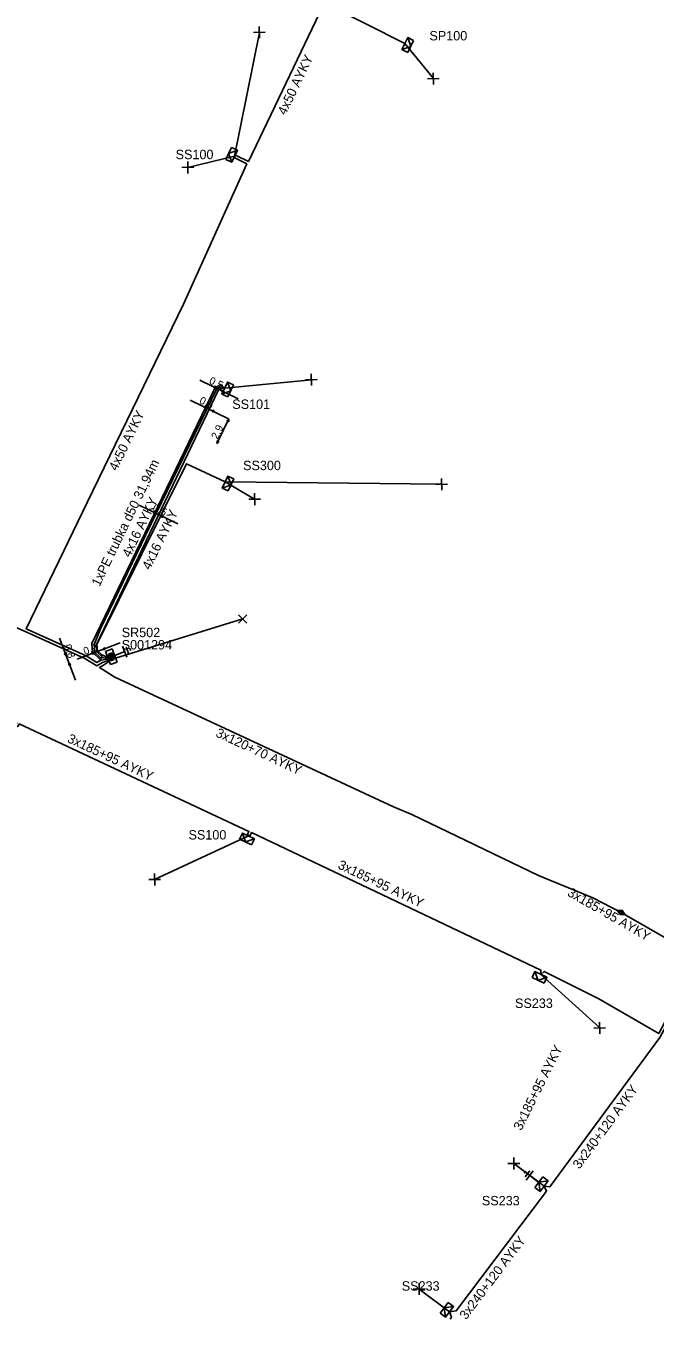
# Model space of a CAD drawing. Extents: x -762500 to -761285, y -1155006 to -1154135.
# Drawn here: x -762111.4 to -762044.9, y -1155000 to -1154863.6 of the extents above; entities that cross this region are included whole.
import ezdxf

# ---------------------------------------------------------------- set-up
doc = ezdxf.new("R2010")
doc.units = 0
for name, color, linetype in [('Vrstva 15', 7, 'Continuous'), ('Vrstva 19', 7, 'Continuous'), ('Vrstva 20', 7, 'Continuous'), ('Vrstva 21', 7, 'Continuous'), ('Vrstva 28', 7, 'Continuous'), ('Vrstva 29', 7, 'Continuous'), ('Vrstva 30', 7, 'Continuous'), ('Vrstva 31', 7, 'Continuous'), ('Vrstva 33', 7, 'Continuous'), ('Vrstva 34', 7, 'Continuous'), ('Vrstva 40', 7, 'Continuous'), ('Vrstva 5', 7, 'Continuous'), ('Vrstva 52', 7, 'Continuous'), ('Vrstva 54', 7, 'Continuous'), ('Vrstva 59', 7, 'Continuous'), ('Vrstva 6', 7, 'Continuous')]:
    doc.layers.add(name, color=color, linetype=linetype)

msp = doc.modelspace()

# ---------------------------------------------------------------- linework, layer by layer
at = {"layer": 'Vrstva 15'}
for points in [[(-762102.074, -1154930.026), (-762100.907, -1154929.578)], [(-762101.131, -1154928.995), (-762100.683, -1154930.162)], [(-762100.755, -1154929.109), (-762100.473, -1154929.844)], [(-762100.372, -1154929.23), (-762100.324, -1154929.354)], [(-762100.324, -1154929.354), (-762100.278, -1154929.474)], [(-762058.711, -1154984.596), (-762058.631, -1154984.49)], [(-762058.631, -1154984.49), (-762058.554, -1154984.388)], [(-762058.61, -1154984.986), (-762058.136, -1154984.358)], [(-762058.508, -1154985.366), (-762057.756, -1154984.367)], [(-762057.133, -1154985.619), (-762058.132, -1154984.866)]]:
    msp.add_lwpolyline(points, dxfattribs=at)
at = {"layer": 'Vrstva 19'}
for points in [[(-762048.601, -1154957.329), (-762048.042, -1154957.351), (-762048.359, -1154956.892), (-762048.917, -1154956.867), (-762048.601, -1154957.329)], [(-762048.157, -1154957.292), (-762048.39, -1154956.947), (-762048.796, -1154956.933), (-762048.571, -1154957.274), (-762048.157, -1154957.292)], [(-762048.268, -1154957.231), (-762048.42, -1154957.002), (-762048.702, -1154956.99), (-762048.54, -1154957.219), (-762048.268, -1154957.231)], [(-762048.374, -1154957.172), (-762048.451, -1154957.057), (-762048.595, -1154957.05), (-762048.51, -1154957.164), (-762048.374, -1154957.172)]]:
    msp.add_lwpolyline(points, dxfattribs=at)
at = {"layer": 'Vrstva 20'}
msp.add_lwpolyline([(-762090.7, -1154901.42), (-762091.37, -1154901.71), (-762104.4, -1154928.74), (-762104.3, -1154929.65), (-762103.52, -1154930.42), (-762103.26, -1154930.18), (-762103.84, -1154929.61), (-762103.9, -1154928.83), (-762091, -1154901.97), (-762090.52, -1154901.77)], close=True, dxfattribs=at)
at = {"layer": 'Vrstva 28'}
for points in [[(-762102.242, -1154929.29), (-762102.942, -1154929.559)], [(-762102.942, -1154929.559), (-762102.405, -1154930.96)], [(-762102.281, -1154929.716), (-762102.634, -1154929.852)], [(-762102.634, -1154929.852), (-762102.367, -1154930.547)], [(-762102.308, -1154929.777), (-762102.573, -1154929.879)], [(-762102.573, -1154929.879), (-762102.34, -1154930.486)], [(-762102.335, -1154929.839), (-762102.512, -1154929.906)], [(-762102.512, -1154929.906), (-762102.313, -1154930.425)], [(-762102.363, -1154929.9), (-762102.451, -1154929.933)], [(-762102.451, -1154929.933), (-762102.286, -1154930.364)], [(-762102.256, -1154930.308), (-762102.392, -1154929.955)], [(-762102.198, -1154930.33), (-762102.363, -1154929.9)], [(-762102.136, -1154930.357), (-762102.335, -1154929.839)], [(-762102.075, -1154930.384), (-762102.308, -1154929.777)], [(-762102.014, -1154930.411), (-762102.281, -1154929.716)], [(-762101.705, -1154930.691), (-762102.242, -1154929.29)], [(-762102.405, -1154930.96), (-762101.705, -1154930.691)], [(-762102.367, -1154930.547), (-762102.014, -1154930.411)], [(-762102.34, -1154930.486), (-762102.075, -1154930.384)], [(-762102.313, -1154930.425), (-762102.136, -1154930.357)], [(-762102.286, -1154930.364), (-762102.198, -1154930.33)]]:
    msp.add_lwpolyline(points, dxfattribs=at)
at = {"layer": 'Vrstva 31'}
for points in [[(-762071.009, -1154866.359), (-762071.638, -1154866.052), (-762071.024, -1154864.794), (-762070.395, -1154865.101)], [(-762070.702, -1154865.73), (-762071.638, -1154866.052)], [(-762070.702, -1154865.73), (-762071.024, -1154864.794)], [(-762071.009, -1154866.359), (-762070.395, -1154865.101)], [(-762089.648, -1154876.397), (-762090.24, -1154877.666)], [(-762089.648, -1154876.397), (-762089.014, -1154876.693), (-762089.605, -1154877.961), (-762090.24, -1154877.666)], [(-762089.944, -1154877.031), (-762089.014, -1154876.693)], [(-762089.944, -1154877.031), (-762089.605, -1154877.961)], [(-762090.013, -1154902.713), (-762090.647, -1154902.417), (-762090.055, -1154901.148), (-762089.421, -1154901.444)], [(-762089.717, -1154902.078), (-762090.055, -1154901.148)], [(-762090.013, -1154902.713), (-762089.421, -1154901.444)], [(-762089.717, -1154902.078), (-762090.647, -1154902.417)], [(-762089.972, -1154912.623), (-762090.606, -1154912.327), (-762090.015, -1154911.059), (-762089.38, -1154911.354)], [(-762089.676, -1154911.989), (-762090.015, -1154911.059)], [(-762089.676, -1154911.989), (-762090.606, -1154912.327)], [(-762089.972, -1154912.623), (-762089.38, -1154911.354)], [(-762088.783, -1154949.367), (-762088.487, -1154948.733), (-762087.218, -1154949.325), (-762087.514, -1154949.959)], [(-762088.148, -1154949.663), (-762088.487, -1154948.733)], [(-762088.783, -1154949.367), (-762087.514, -1154949.959)], [(-762088.148, -1154949.663), (-762087.218, -1154949.325)], [(-762057.893, -1154963.978), (-762057.597, -1154963.344), (-762056.328, -1154963.935), (-762056.624, -1154964.57)], [(-762057.893, -1154963.978), (-762056.624, -1154964.57)], [(-762057.258, -1154964.274), (-762057.597, -1154963.344)], [(-762057.258, -1154964.274), (-762056.328, -1154963.935)], [(-762056.756, -1154985.017), (-762057.599, -1154986.135)], [(-762056.756, -1154985.017), (-762056.197, -1154985.438), (-762057.04, -1154986.557), (-762057.599, -1154986.135)], [(-762057.178, -1154985.576), (-762056.197, -1154985.438)], [(-762057.178, -1154985.576), (-762057.04, -1154986.557)], [(-762066.756, -1154998.267), (-762067.599, -1154999.385)], [(-762066.756, -1154998.267), (-762066.197, -1154998.688), (-762067.04, -1154999.807), (-762067.599, -1154999.385)], [(-762067.178, -1154998.826), (-762066.197, -1154998.688)], [(-762067.178, -1154998.826), (-762067.04, -1154999.807)]]:
    msp.add_lwpolyline(points, dxfattribs=at)
at = {"layer": 'Vrstva 34'}
for points in [[(-762087.315, -1154864.261), (-762086.065, -1154864.239)], [(-762086.679, -1154864.875), (-762086.701, -1154863.625)], [(-762068.299, -1154869.755), (-762068.321, -1154868.505)], [(-762068.935, -1154869.141), (-762067.685, -1154869.119)], [(-762094.239, -1154879.125), (-762094.261, -1154877.875)], [(-762094.875, -1154878.511), (-762093.625, -1154878.489)], [(-762081.825, -1154900.911), (-762080.575, -1154900.889)], [(-762081.189, -1154901.525), (-762081.211, -1154900.275)], [(-762068.055, -1154911.941), (-762066.805, -1154911.919)], [(-762067.419, -1154912.555), (-762067.441, -1154911.305)], [(-762087.815, -1154913.511), (-762086.565, -1154913.489)], [(-762087.179, -1154914.125), (-762087.201, -1154912.875)], [(-762088.882, -1154925.688), (-762087.998, -1154926.572)], [(-762088.882, -1154926.572), (-762087.998, -1154925.688)], [(-762097.739, -1154954.255), (-762097.761, -1154953.005)], [(-762098.375, -1154953.641), (-762097.125, -1154953.619)], [(-762051.375, -1154969.301), (-762050.125, -1154969.279)], [(-762050.739, -1154969.915), (-762050.761, -1154968.665)], [(-762059.799, -1154984.215), (-762059.821, -1154982.965)], [(-762060.435, -1154983.601), (-762059.185, -1154983.579)], [(-762070.435, -1154996.851), (-762069.185, -1154996.829)], [(-762069.799, -1154997.465), (-762069.821, -1154996.215)]]:
    msp.add_lwpolyline(points, dxfattribs=at)
at = {"layer": 'Vrstva 40'}
for points in [[(-762088.94, -1154902.92), (-762092.97, -1154900.95)], [(-762089.96, -1154905.01), (-762094, -1154903.04)], [(-762091.17, -1154907.63), (-762089.9, -1154905.04)], [(-762099.39, -1154914.15), (-762095.31, -1154916.09)], [(-762106.1, -1154932.6), (-762107.8, -1154928.15)], [(-762101.39, -1154928.66), (-762105.94, -1154930.39)]]:
    msp.add_lwpolyline(points, dxfattribs=at)
for points in [[(-762091.168, -1154901.831), (-762091.437, -1154901.821), (-762091.349, -1154901.631)], [(-762090.742, -1154902.039), (-762090.473, -1154902.049), (-762090.561, -1154902.239)], [(-762092.198, -1154903.921), (-762092.467, -1154903.911), (-762092.379, -1154903.721)], [(-762091.762, -1154904.139), (-762091.493, -1154904.149), (-762091.581, -1154904.339)], [(-762089.899, -1154905.038), (-762089.909, -1154905.307), (-762090.099, -1154905.219)], [(-762091.171, -1154907.632), (-762091.161, -1154907.363), (-762090.971, -1154907.451)], [(-762097.578, -1154915.011), (-762097.847, -1154915.001), (-762097.759, -1154914.811)], [(-762097.122, -1154915.229), (-762096.853, -1154915.239), (-762096.941, -1154915.429)], [(-762107.089, -1154930.023), (-762107.276, -1154929.828), (-762107.08, -1154929.753)], [(-762104.068, -1154929.679), (-762104.262, -1154929.866), (-762104.337, -1154929.671)], [(-762103.262, -1154929.371), (-762103.068, -1154929.184), (-762102.993, -1154929.379)], [(-762106.82, -1154930.728), (-762106.634, -1154930.922), (-762106.829, -1154930.997)]]:
    msp.add_lwpolyline(points, close=True, dxfattribs=at)
at = {"layer": 'Vrstva 5'}
for points in [[(-762102.72, -1154930.4), (-762103.42, -1154930.5), (-762103.86, -1154930.73), (-762104.97, -1154930.03), (-762111.33, -1154927.18), (-762104.86, -1154913.86), (-762094.7, -1154892.93), (-762088.02, -1154878.13), (-762089.28, -1154877.5), (-762089.31, -1154877.33), (-762089.14, -1154877.24), (-762087.84, -1154877.87), (-762077.14, -1154855.52), (-762078.88, -1154854.61), (-762079.02, -1154854.2)], [(-762079.02, -1154854.2), (-762076.74, -1154855.39), (-762079.56, -1154861.27), (-762071.33, -1154865.42)], [(-762102.85, -1154930.14), (-762103.31, -1154929.93), (-762103.77, -1154929.52), (-762103.86, -1154928.82), (-762094.39, -1154909.77), (-762090.31, -1154911.69)], [(-762128.78, -1154919.4), (-762128.84, -1154919.72), (-762110.73, -1154927.77), (-762105.11, -1154930.3), (-762103.87, -1154931.08), (-762103.27, -1154930.75), (-762102.67, -1154930.54)], [(-762135.97, -1154927.36), (-762135.55, -1154926.14), (-762112.32, -1154937.09), (-762112.43, -1154937.34), (-762112.35, -1154937.52), (-762112.16, -1154937.46), (-762112.05, -1154937.21), (-762087.8, -1154948.55), (-762087.93, -1154948.83), (-762087.85, -1154949.03), (-762087.66, -1154948.97), (-762087.52, -1154948.67), (-762056.95, -1154963.18), (-762056.96, -1154963.64)], [(-762102.61, -1154930.68), (-762103.14, -1154931.02), (-762103.59, -1154931.26), (-762101.97, -1154932.27), (-762072.52, -1154945.96), (-762070.58, -1154946.78), (-762057.2, -1154953.22), (-762051.46, -1154955.56), (-762048.48, -1154957.11)], [(-762048.48, -1154957.11), (-762040.57, -1154961.64), (-762040.21, -1154961.46)], [(-762039.98, -1154961.58), (-762039.86, -1154961.99), (-762044.4, -1154970.29), (-762056.02, -1154986.07), (-762056.62, -1154986), (-762056.37, -1154986.51), (-762065.89, -1154999.15), (-762066.62, -1154999.25)], [(-762056.96, -1154963.64), (-762056.61, -1154963.33), (-762050.84, -1154966.21), (-762044.51, -1154969.87), (-762040.1, -1154961.52)], [(-762066.62, -1154999.25), (-762066.4, -1154999.8), (-762066.55, -1155000)]]:
    msp.add_lwpolyline(points, dxfattribs=at)
at = {"layer": 'Vrstva 52'}
msp.add_lwpolyline([(-762102.78, -1154930.26), (-762103.5, -1154930.2), (-762104.07, -1154929.68), (-762104.15, -1154928.85), (-762103.45, -1154927.11), (-762098.7, -1154917.33), (-762091.17, -1154901.83), (-762090.66, -1154901.62), (-762090.35, -1154901.78)], dxfattribs=at)
at = {"layer": 'Vrstva 59'}
for points in [[(-762089.31, -1154877.33), (-762086.69, -1154864.25)], [(-762071.33, -1154865.42), (-762068.31, -1154869.13)], [(-762089.31, -1154877.33), (-762094.25, -1154878.5)], [(-762090.35, -1154901.78), (-762081.2, -1154900.9)], [(-762090.31, -1154911.69), (-762067.43, -1154911.93)], [(-762090.31, -1154911.69), (-762087.19, -1154913.5)], [(-762101.87, -1154930.28), (-762088.44, -1154926.13)], [(-762087.85, -1154949.03), (-762097.75, -1154953.63)], [(-762056.96, -1154963.64), (-762050.75, -1154969.29)], [(-762056.62, -1154986), (-762059.81, -1154983.59)], [(-762066.62, -1154999.25), (-762069.81, -1154996.84)]]:
    msp.add_lwpolyline(points, dxfattribs=at)

# ---------------------------------------------------------------- texts
at = {"layer": 'Vrstva 21'}
msp.add_text('1xPE trubka d50 31,94m', height=0.99429, rotation=64.26411, dxfattribs=at).set_placement((-762103.57, -1154922.79))
at = {"layer": 'Vrstva 29'}
msp.add_text('S001294', height=0.9943, dxfattribs=at).set_placement((-762101.23, -1154929.36))
at = {"layer": 'Vrstva 30'}
msp.add_text('SR502', height=0.9943, dxfattribs=at).set_placement((-762101.23, -1154928.06))
at = {"layer": 'Vrstva 33'}
for s, p in [('SP100', (-762068.73, -1154865.1)), ('SS100', (-762095.53, -1154877.63)), ('SS101', (-762089.55, -1154903.98)), ('SS300', (-762088.41, -1154910.44)), ('SS100', (-762094.17, -1154949.41)), ('SS233', (-762059.69, -1154967.18)), ('SS233', (-762063.19, -1154988.01)), ('SS233', (-762071.65, -1154997.01))]:
    msp.add_text(s, height=0.9943, dxfattribs=at).set_placement(p)
at = {"layer": 'Vrstva 40'}
for s, rotation, p in [('0,5', 334.02058, (-762092.07, -1154901.26)), ('0,5', 334.00328, (-762093.1, -1154903.35)), ('2,9', 64.03988, (-762091.11, -1154907.24)), ('0,5', 334.5952, (-762098.03, -1154914.67)), ('0,8', 290.89062, (-762107.36, -1154928.99)), ('0,9', 20.91799, (-762105.1, -1154929.95))]:
    msp.add_text(s, height=0.7954, rotation=rotation, dxfattribs=at).set_placement(p)
at = {"layer": 'Vrstva 54'}
msp.add_text('4x16 AYKY', height=0.9943, rotation=64.26929, dxfattribs=at).set_placement((-762100.35, -1154919.72))
at = {"layer": 'Vrstva 6'}
for s, height, rotation, p in [('4x50 AYKY', 0.9943, 64.42021, (-762083.92, -1154873.05)), ('4x50 AYKY', 0.9943, 64.10349, (-762101.75, -1154910.58)), ('4x16 AYKY', 0.9943, 63.87633, (-762098.25, -1154921.03)), ('3x185+95 AYKY', 0.99429, 334.94082, (-762107.05, -1154939.1)), ('3x120+70 AYKY', 0.99429, 335.06837, (-762091.38, -1154938.5)), ('3x185+95 AYKY', 0.99429, 334.61243, (-762078.48, -1154952.42)), ('3x185+95 AYKY', 0.99429, 330.22945, (-762054.24, -1154955.29)), ('3x185+95 AYKY', 0.99429, 63.4429, (-762059.03, -1154980.19)), ('3x240+120 AYKY', 0.99429, 53.62419, (-762052.89, -1154984.25)), ('3x240+120 AYKY', 0.99429, 53.02724, (-762064.85, -1155000.14))]:
    msp.add_text(s, height=height, rotation=rotation, dxfattribs=at).set_placement(p)

doc.saveas('drawing.dxf')
